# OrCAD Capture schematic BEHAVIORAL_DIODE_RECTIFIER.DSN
size A
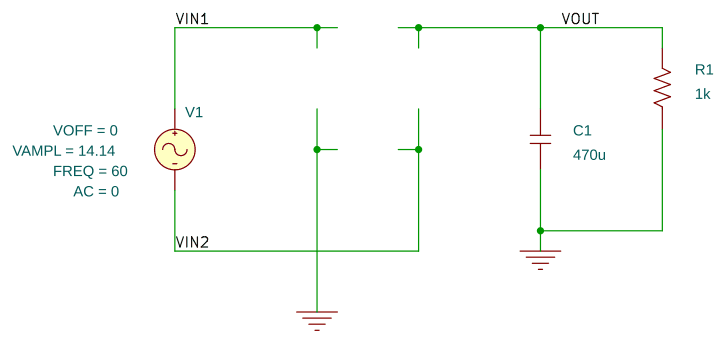
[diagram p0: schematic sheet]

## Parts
C1  470u  [cap196]
R1  1k  [AXRC05]
V1  VSIN

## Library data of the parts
C1 = C
R1 = R
V1 = VSIN: AC: 0; FREQ: 60; VAMPL: 14.14; VOFF: 0

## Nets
VIN1: V1.1(+)
VIN2: V1.2(-)
0: C1.1 R1.1
VOUT: C1.2 R1.2
